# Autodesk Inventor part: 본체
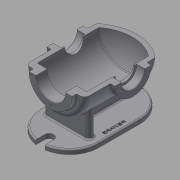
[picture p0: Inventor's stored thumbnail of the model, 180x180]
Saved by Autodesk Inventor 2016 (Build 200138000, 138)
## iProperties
Created: 2016-02
Part Number: 본체
Material: 일반
Document SubType Name: Modeling
Designer: mduedu
Density: 2.71 g/cm^3
Appearance: 기본값
Author: mduedu
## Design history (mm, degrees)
sketch "스케치2"
  geometry: L1 (0, 90)-(0, -90); L2 (65, -65.993)-(65, 90); L3 (65, 90)-(0, 90); A1 r 100 centre (0, 10) between (0, -90) and (65, -65.993); 2 further points
  constraints: 6 end point, 2 point on circle, 1 centre point, 1 coincident, 1 horizontal, 1 midpoint, 1 parallel, 1 point on line, 1 vertical
  dimensions: "d3" = 180 distance of L1.start L1.end; "d5" = 130 diameter of L2 L1; "d6" = 100 radius of A1
revolve "회전1" sketch "스케치2" stored, may be unused: angle "d7" = 90 deg
sketch "스케치3"
  geometry: C1 r 47.5 at (0, 0); 1 further point
  constraints: 1 centre point, 1 coincident
  dimensions: "d8" = 95 diameter of C1
extrude "돌출2" join sketch "스케치3" distance "d10" = 10; taper "d11" = 0 deg
sketch "스케치5"
  geometry: L1 (47.5, 100)-(47.5, 90) reference; L2 (47.5, 90)-(65, 90) reference; L3 (65, 90)-(65, -65.993) reference; L4 (-65, -65.993)-(-65, 90) reference; L5 (-65, 90)-(-47.5, 90) reference; L6 (-47.5, 90)-(-47.5, 100) reference; L7 (-47.5, 100)-(47.5, 100) reference; L8 (55, 75)-(55, -61.239); L9 (0, 75)-(55, 75); L10 (0, 75)-(0, -80); A1 r 100 centre (0, 10) between (-65, -65.993) and (0, -90) reference; A2 r 100 centre (0, 10) between (0, -90) and (65, -65.993) reference; A3 r 90 centre (0, 10) between (0, -80) and (55, -61.239); 1 further point
  constraints: 6 end point, 2 point on circle, 1 centre point, 1 parallel, 1 perpendicular, 1 point on line, 1 vertical
  dimensions: "d13" = 10 distance between parallel lines of L3 L8; "d14" = 10 radial gap between concentric circles of A3 A1; "d15" = 15 distance between parallel lines of L9 L2
revolve "회전2" sketch "스케치5" stored, may be unused: angle "d16" = 90 deg
hole "구멍1" diameter "d19" = 65; stored, may be unused: countersink angle "d23" = 90 deg, drill point angle "d25" = 118 deg; dims "d17" = 10, "d18" = 10, "d20" = 6, "d21" = 4, "d22" = 2, "d24" = 8
node "작업 평면1"
sketch "스케치6"
  geometry: L1 (47.5, 100)-(-47.5, 100) reference; C1 r 40 at (0, -7); 1 further point
  constraints: 1 centre point, 1 vertical alignment
  dimensions: "d27" = 80 diameter of C1; "d29" = 107 distance from line of C1.centre L1
extrude "돌출3" join sketch "스케치6" stored distance "d30" = 10; taper "d31" = 0 deg
hole "구멍2" diameter "d34" = 42; stored, may be unused: countersink angle "d38" = 90 deg, drill point angle "d40" = 118 deg; dims "d32" = 10, "d33" = 10, "d35" = 6, "d36" = 52, "d37" = 18, "d39" = 8
sketch "스케치7" dims "d41" = 65
  geometry: C1 r 40 at (0, 0) reference; 3 further points
  constraints: 2 vertical alignment, 1 coincident, 2 other
hole "구멍3" sketch "스케치7" at (0, 32.5) diameter "d43" = 3.242; stored, may be unused: countersink angle "d47" = 90 deg, drill point angle "d49" = 118 deg; dims "d44" = 11, "d45" = 13, "d46" = 18, "d48" = 13
sketch "스케치8" dims "d53" = 80
  geometry: 3 further points
  constraints: 2 vertical alignment, 1 coincident, 2 other
hole "구멍4" sketch "스케치8" at (0, -40) diameter "d56" = 3.242; stored, may be unused: countersink angle "d60" = 90 deg, drill point angle "d62" = 118 deg; dims "d57" = 11, "d58" = 13, "d59" = 18, "d61" = 13
fillet "모깎기1" dims "d66" = 10
fillet "모깎기2" dims "d67" = 3
fillet "모깎기3" dims "d68" = 0.3
chamfer "모따기1" distance "d69" = 1; stored, may be unused: second distance "d70" = 2, angle "d71" = 45 deg
node "작업 평면5"
sketch "스케치10"
  geometry: L1 (-50, 66)-(50, 66); L2 (50, 66)-(50, 50); L3 (50, 50)-(-50, 50); L4 (-50, 50)-(-50, 66); 2 further points
  constraints: 8 end point, 2 horizontal, 2 vertical, 1 midpoint, 1 vertical alignment
  dimensions: "d177" = 50 distance from line of L3 point (0, 0); "d178" = 100 distance of L1.start L1.end; "d179" = 16 distance of L3.end L1.start
extrude "돌출5" join sketch "스케치10" stored distance "d84" = 10; taper "d85" = 0 deg
sketch "스케치21" dims "d180" = 220, "d182" = 130
  geometry: L1 (65, 58)-(-65, 58); L2 (-65, 58)-(-65, -32); L3 (-65, -32)-(65, -32); L4 (65, -32)-(65, 58); L5 (50, 50)-(50, 66) reference; 4 further points
  constraints: 8 end point, 3 horizontal alignment, 3 midpoint, 2 parallel, 1 horizontal, 1 perpendicular, 1 vertical alignment, 4 other
extrude "돌출13" join sketch "스케치21" distance "d183" = 10; taper "d184" = 0 deg
sketch "스케치11"
  geometry: L1 (-65, 80)-(-65, -61.239) reference; L2 (-100, -97)-(-100, -32) reference; L3 (-65, -42.793)-(-100, -63); L4 (-100, -97)-(-110, -97) reference; 1 further point
  constraints: 2 end point, 2 point on line
  dimensions: "d185" = 34 distance from line of L3.end L4; "d186" = 120 deg angle of L2 L3
feature "리브1" sketch "스케치11" dims "d88" = 1, "d89" = 16, "d90" = 0, "d91" = 0, "d92" = 1, "d93" = 1
fillet "모깎기12"
fillet "모깎기13"
fillet "모깎기16" dims "d167" = 3
fillet "모깎기18"
fillet "모깎기17" dims "d168" = 3
fillet "모깎기19" dims "d187" = 3
node "작업 평면6"
sketch "스케치19"
  geometry: L1 (75, -47)-(75, 33) reference; L2 (-75, -47)-(-75, 33) reference; L3 (75, -7)-(-75, -7); C1 r 22.5 at (0, -7); 1 further point
  constraints: 3 midpoint, 2 end point, 1 centre point
  dimensions: "d149" = 45 diameter of C1
extrude "돌출11" join sketch "스케치19" stored distance "d150" = 10; taper "d151" = 0 deg
hole "구멍6" diameter "d154" = 33.376; stored, may be unused: countersink angle "d158" = 90 deg, drill point angle "d160" = 118 deg; dims "d155" = 6, "d156" = 4, "d157" = 2, "d159" = 8, "d190" = 10, "d191" = 10
fillet "모깎기11" dims "d161" = 3
chamfer "모따기3" distance "d164" = 1; stored, may be unused: second distance "d165" = 2, angle "d166" = 45 deg
node "작업 평면9"
  node "작업 평면8"
sketch "스케치22" dims "d189" = 20
  geometry: L1 (-10, -123)-(10, -123); L2 (10, -123)-(10, -103); L3 (10, -103)-(-10, -103); L4 (-10, -103)-(-10, -123); A1 r 65 centre (0, -58) between (-65, -58) and (65, -58) reference; 2 further points
  constraints: 8 end point, 2 parallel, 1 horizontal, 1 horizontal alignment, 1 midpoint, 1 perpendicular, 1 tangent, 1 vertical alignment, 2 other
  dimensions: "d193" = 30 dimension on L1
extrude "돌출14" cut sketch "스케치22" stored distance "d194" = 10; taper "d195" = 0 deg
fillet "모깎기21" dims "d196" = 3
feature "분할1"
sketch "스케치23"
  geometry: L1 (-65, 32)-(-65, -58) reference; L2 (65, -58)-(65, 32) reference; L3 (-65, -13)-(65, -13); 2 further points
  constraints: 2 end point, 2 midpoint, 1 point on line, 1 other
  dimensions: "d197" = 12 distance from line of point (53, -13) L2
feature "엠보싱2" sketch "스케치23" dims "d8" = 95, "d198" = 0.5, "d199" = 0
node "솔리드2"
pattern_circular "원형 패턴1" dims angle "d51" = 360 deg
mirror "대칭1"
pattern_circular "원형 패턴2" dims angle "d64" = 360 deg
mirror "대칭3"
node "절단 모서리 투영1"
other parameters: "d26" = 75, "d136" = 175
